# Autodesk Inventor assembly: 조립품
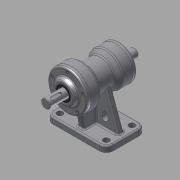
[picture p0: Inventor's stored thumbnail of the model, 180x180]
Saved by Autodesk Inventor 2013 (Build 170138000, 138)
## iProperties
Created: 2015-08
Part Number: 조립품
Document SubType Name: Assembly
Designer: ST4
Author: ST4
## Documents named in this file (10)
- C:\Users\ST4\Desktop\450805V1019\조립품.iam
- C:\Users\ST4\Desktop\450805V1019\본체.ipt
- C:\Users\ST4\Desktop\450805V1019\M4x0.5.ipt
- C:\Users\ST4\Desktop\450805V1019\뒤커버.ipt
- C:\Users\ST4\Desktop\450805V1019\베어링 6203.ipt
- C:\Users\ST4\Desktop\450805V1019\베어링 6205.ipt
- C:\Users\ST4\Desktop\450805V1019\앞커버.ipt
- C:\Users\ST4\Desktop\450805V1019\오일실 .ipt
- 오일실 .ipt
- C:\Users\ST4\Desktop\450805V1019\축.ipt
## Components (10 placed, 1 different names)
1. M4x0.5:1
2. M4x0.5:2
3. M4x0.5:3
4. M4x0.5:4
5. M4x0.5:5
6. M4x0.5:6
7. M4x0.5:7
8. M4x0.5:8
9. M4x0.5:9
10. M4x0.5:10
